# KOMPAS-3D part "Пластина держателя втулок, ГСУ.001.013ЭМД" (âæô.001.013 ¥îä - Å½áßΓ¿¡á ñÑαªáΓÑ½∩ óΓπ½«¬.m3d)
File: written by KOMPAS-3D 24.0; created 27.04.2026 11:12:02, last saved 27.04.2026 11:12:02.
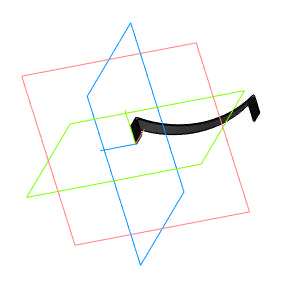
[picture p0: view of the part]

Document properties: Автор: USG_411; Полное имя файла: C:\Users\USG_411\Desktop\ГМ2704_411-15\Двигатель мясорубки\ГСУ.001.013 ЭМД - Пластина держателя втулок.m3d

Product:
- Part/product: Пластина держателя втулок  | designation ГСУ.001.013ЭМД
    Масса: 0.000654

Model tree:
1. Эскиз:1
2. Элемент выдавливания:1
     Толщина стенки 1 = 0.3; Расстояние 1 = 6
3. Скругление:1  (with: Ребро.Элемент выдавливания:1)
     Радиус = 0.3

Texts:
  ГСУ.001.013
  ГСУ.001.013 ЭМД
